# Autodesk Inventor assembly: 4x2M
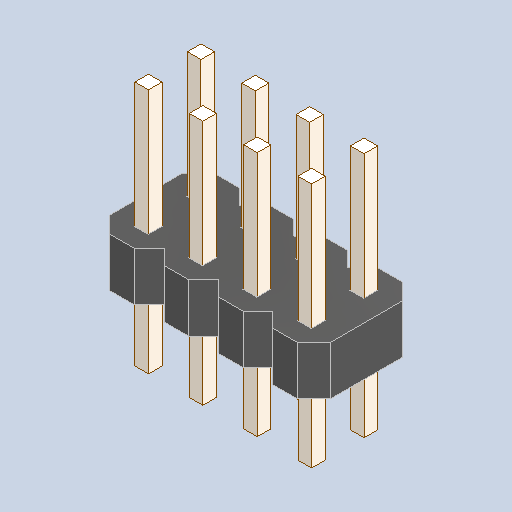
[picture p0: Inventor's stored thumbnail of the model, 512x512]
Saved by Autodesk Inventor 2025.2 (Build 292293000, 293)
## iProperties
Created: 2025-04
Part Number: 4x2M
Description: PART--DESC
Document SubType Name: Assembly
Designer: BennF
Author: BennF
Revision Number: NONE
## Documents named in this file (3)
- C:\Users\BennF\Nextcloud\Benutzer\CNC JarBeRi\existing parts\Electronics\RepRap A4988 Shied (USE WITHOUT ARDUINO)\reprap-a4988-1.snapshot.1\RepRap\RepRap\4x2M_2.iam
- C:\Users\BennF\Nextcloud\Benutzer\CNC JarBeRi\existing parts\Electronics\RepRap A4988 Shied (USE WITHOUT ARDUINO)\reprap-a4988-1.snapshot.1\RepRap\RepRap\4x2M Geometry.ipt
- C:\Users\BennF\Nextcloud\Benutzer\CNC JarBeRi\existing parts\Electronics\RepRap A4988 Shied (USE WITHOUT ARDUINO)\reprap-a4988-1.snapshot.1\RepRap\RepRap\pin8.ipt
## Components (2 placed, 2 different names)
1. 4x2M Geometry
2. pin8
